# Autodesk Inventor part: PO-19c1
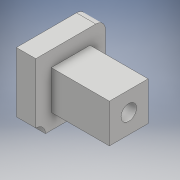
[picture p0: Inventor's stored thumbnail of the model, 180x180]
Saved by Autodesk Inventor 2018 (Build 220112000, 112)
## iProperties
Created: 2020-01
Part Number: PO-19c1
Material: Générique
Document SubType Name: Modeling
Designer: TJ
Density: 1 g/cm^3
Appearance: Par défaut
Author: TJ
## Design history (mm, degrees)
sketch "Esquisse1"
  geometry: L1 (18, 18)-(-18, 18); L2 (-18, 18)-(-18, -18); L3 (-18, -18)-(18, -18); L4 (18, -18)-(18, 18); 1 further point
  constraints: 8 end point, 2 parallel, 1 horizontal, 1 perpendicular
  dimensions: "d0" = 36 distance of L3.end L1.start; "d1" = 36 distance of L1.start L1.end (= d0); "d2" = 18 distance from line of L4 point (0, 0) (= 0.5 x d0); "d3" = 18 distance from line of L1 point (0, 0) (= 0.5 x d0)
extrude "Extrusion1" new body sketch "Esquisse1" distance "d4" = 10; taper "d5" = 0 deg
sketch "Esquisse3"
  geometry: L1 (-10, 10)-(10, 10); L2 (10, 10)-(10, -10); L3 (10, -10)-(-10, -10); L4 (-10, -10)-(-10, 10); L5 (-10, 10)-(10, -10); L6 (10, 10)-(-10, -10); 1 further point
  constraints: 12 end point, 2 midpoint, 2 parallel, 1 horizontal, 1 perpendicular
  dimensions: "d10" = 20 distance of L1.start L1.end; "d11" = 20 distance of L3.end L1.start (= d10)
extrude "Extrusion3" join sketch "Esquisse3" distance "d12" = 30; taper "d13" = 0 deg
sketch "Esquisse5"
  geometry: L1 (-4, -4)-(4, -4); L2 (4, -4)-(4, 4); L3 (4, 4)-(-4, 4); L4 (-4, 4)-(-4, -4); L5 (-4, -4)-(4, 4); L6 (4, -4)-(-4, 4); 1 further point
  constraints: 12 end point, 2 midpoint, 2 parallel, 1 horizontal, 1 perpendicular
  dimensions: "d17" = 8 distance of L3.end L1.start; "d18" = 8 distance of L2.end L3.end
extrude "Extrusion5" cut sketch "Esquisse5" extent not by distance; stored distance "d19" = 10; taper "d20" = 0 deg
fillet "Congé2" dims "d21" = 5
fillet "Congé3" dims "d25" = 4
sketch "Esquisse6"
  geometry: L1 (-18, -18)-(18, -18) reference; C1 r 5 at (18, -18); 1 further point
  constraints: 1 centre point
  dimensions: "d26" = 10 diameter of C1
extrude "Extrusion6" cut sketch "Esquisse6" extent not by distance; stored distance "d27" = 10; taper "d28" = 0 deg
node "Solide1"
